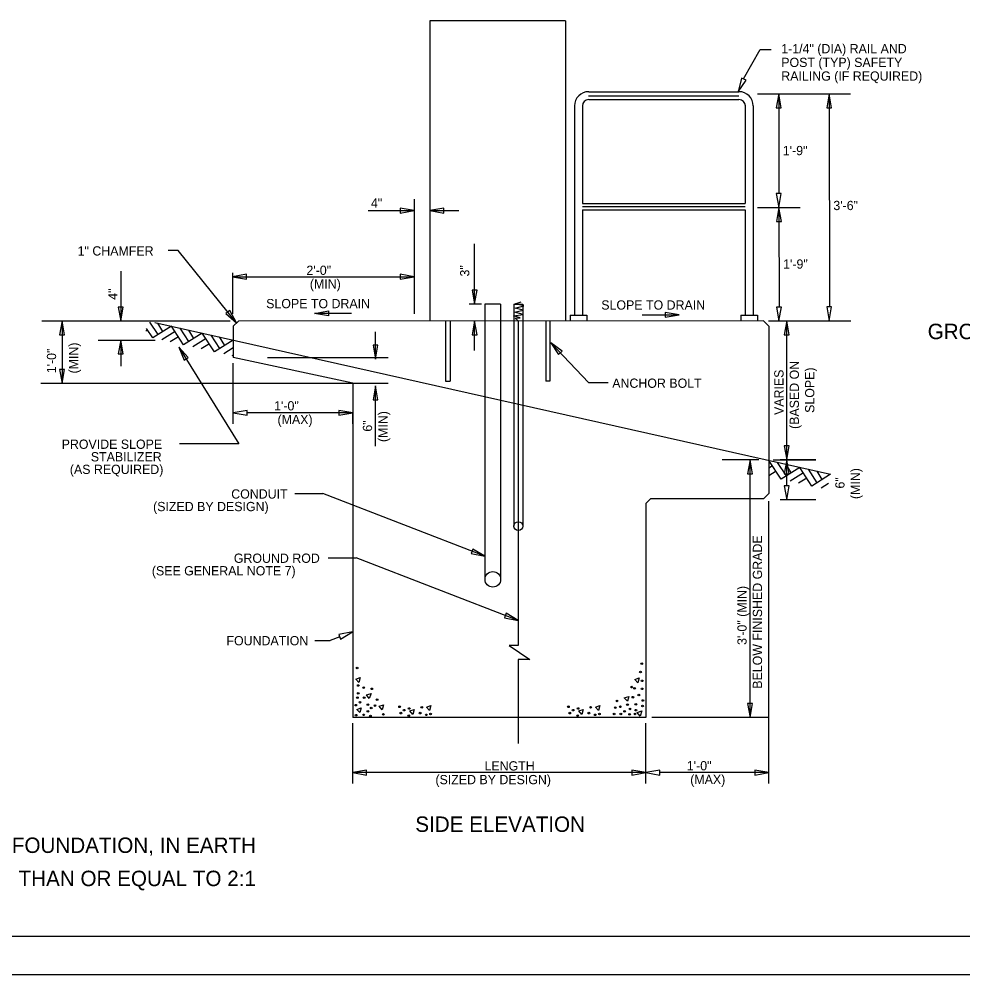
# Model space of a CAD drawing. Extents: x 1299104.8 to 1299141.6, y 239639.8 to 239661.8.
# Drawn here: x 1299117.69 to 1299129.92, y 239639.79 to 239652.18 of the extents above; entities that cross this region are included whole.
import ezdxf

# ---------------------------------------------------------------- set-up
doc = ezdxf.new("R2010")
doc.units = 0
for name, color, linetype in [('GS_plotshape_p', 7, 'Continuous'), ('Level 1', 7, 'Continuous'), ('PTEXT', 7, 'Continuous')]:
    doc.layers.add(name, color=color, linetype=linetype)

msp = doc.modelspace()

# ---------------------------------------------------------------- linework, layer by layer
at = {"layer": 'GS_plotshape_p'}
msp.add_lwpolyline([(1299104.802, 239661.791), (1299138.802, 239661.791), (1299138.802, 239639.791), (1299104.802, 239639.791)], close=True, dxfattribs=at)
at = {"layer": 'Level 1'}
msp.add_lwpolyline([(1299138.302, 239640.291), (1299106.302, 239640.291), (1299106.302, 239661.291), (1299138.302, 239661.291)], close=True, dxfattribs=at)
at = {"layer": 'PTEXT'}
for p, q in [((1299123.016, 239652.158), (1299123.016, 239648.269)), ((1299124.772, 239652.158), (1299123.016, 239652.158)), ((1299124.772, 239652.158), (1299124.772, 239648.269)), ((1299127.055, 239651.418), (1299127.01, 239651.241)), ((1299127.01, 239651.241), (1299127.113, 239651.392)), ((1299127.113, 239651.392), (1299127.055, 239651.418)), ((1299125.073, 239651.189), (1299127.022, 239651.189)), ((1299125.075, 239651.241), (1299127.021, 239651.241)), ((1299125.075, 239651.139), (1299127.021, 239651.139)), ((1299127.262, 239651.212), (1299127.812, 239651.212)), ((1299127.264, 239651.212), (1299128.467, 239651.212)), ((1299127.537, 239651.212), (1299127.505, 239651.032)), ((1299127.537, 239651.212), (1299127.537, 239649.92)), ((1299127.568, 239651.032), (1299127.537, 239651.212)), ((1299128.192, 239651.212), (1299128.16, 239651.032)), ((1299128.192, 239651.212), (1299128.194, 239648.451)), ((1299128.223, 239651.032), (1299128.192, 239651.212)), ((1299124.89, 239651.056), (1299124.89, 239648.345)), ((1299124.992, 239651.056), (1299124.992, 239649.793)), ((1299127.104, 239651.057), (1299127.104, 239649.793)), ((1299127.206, 239651.056), (1299127.206, 239648.345)), ((1299127.505, 239651.032), (1299127.568, 239651.032)), ((1299128.16, 239651.032), (1299128.223, 239651.032)), ((1299127.505, 239649.92), (1299127.537, 239649.74)), ((1299127.568, 239649.92), (1299127.505, 239649.92)), ((1299127.537, 239649.74), (1299127.568, 239649.92)), ((1299122.81, 239649.848), (1299122.81, 239648.363)), ((1299124.992, 239649.793), (1299127.104, 239649.793)), ((1299122.217, 239649.699), (1299122.81, 239649.699)), ((1299122.81, 239649.699), (1299122.63, 239649.731)), ((1299122.63, 239649.731), (1299122.63, 239649.668)), ((1299122.63, 239649.668), (1299122.81, 239649.699)), ((1299123.196, 239649.731), (1299123.016, 239649.699)), ((1299123.016, 239649.699), (1299123.392, 239649.699)), ((1299123.016, 239649.699), (1299123.196, 239649.668)), ((1299123.196, 239649.668), (1299123.196, 239649.731)), ((1299124.992, 239649.753), (1299127.104, 239649.753)), ((1299124.992, 239649.709), (1299124.992, 239648.345)), ((1299124.992, 239649.709), (1299127.104, 239649.709)), ((1299127.104, 239649.709), (1299127.104, 239648.345)), ((1299127.262, 239649.74), (1299127.812, 239649.74)), ((1299127.265, 239649.74), (1299127.815, 239649.74)), ((1299127.54, 239649.74), (1299127.509, 239649.56)), ((1299127.54, 239649.74), (1299127.541, 239648.449)), ((1299127.572, 239649.56), (1299127.54, 239649.74)), ((1299127.509, 239649.56), (1299127.572, 239649.56)), ((1299123.594, 239648.489), (1299123.594, 239649.267)), ((1299119.007, 239648.913), (1299119.007, 239648.269)), ((1299120.458, 239648.891), (1299120.458, 239648.36)), ((1299120.638, 239648.874), (1299120.458, 239648.842)), ((1299120.458, 239648.842), (1299122.81, 239648.842)), ((1299120.458, 239648.842), (1299120.638, 239648.81)), ((1299120.638, 239648.81), (1299120.638, 239648.874)), ((1299122.81, 239648.842), (1299122.63, 239648.874)), ((1299122.63, 239648.874), (1299122.63, 239648.81)), ((1299122.63, 239648.81), (1299122.81, 239648.842)), ((1299123.563, 239648.669), (1299123.594, 239648.489)), ((1299123.626, 239648.669), (1299123.563, 239648.669)), ((1299123.594, 239648.489), (1299123.626, 239648.669)), ((1299118.975, 239648.449), (1299119.007, 239648.269)), ((1299119.038, 239648.449), (1299118.975, 239648.449)), ((1299119.007, 239648.269), (1299119.038, 239648.449)), ((1299123.526, 239648.489), (1299123.683, 239648.489)), ((1299123.932, 239648.488), (1299123.729, 239648.488)), ((1299123.729, 239648.488), (1299123.729, 239648.269)), ((1299123.932, 239648.488), (1299123.932, 239648.269)), ((1299124.103, 239648.488), (1299124.103, 239645.609)), ((1299124.103, 239648.488), (1299124.219, 239648.488)), ((1299124.219, 239648.488), (1299124.219, 239645.609)), ((1299127.509, 239648.449), (1299127.54, 239648.269)), ((1299127.572, 239648.449), (1299127.509, 239648.449)), ((1299127.54, 239648.269), (1299127.572, 239648.449)), ((1299128.16, 239648.451), (1299128.192, 239648.271)), ((1299128.223, 239648.451), (1299128.16, 239648.451)), ((1299128.192, 239648.271), (1299128.223, 239648.451)), ((1299120.422, 239648.405), (1299120.372, 239648.366)), ((1299120.372, 239648.366), (1299120.509, 239648.245)), ((1299120.509, 239648.245), (1299120.422, 239648.405)), ((1299121.52, 239648.366), (1299121.7, 239648.398)), ((1299122, 239648.366), (1299121.52, 239648.366)), ((1299121.7, 239648.334), (1299121.52, 239648.366)), ((1299121.7, 239648.398), (1299121.7, 239648.334)), ((1299124.832, 239648.345), (1299125.05, 239648.345)), ((1299124.832, 239648.345), (1299124.832, 239648.269)), ((1299125.05, 239648.345), (1299125.05, 239648.269)), ((1299125.766, 239648.348), (1299126.245, 239648.348)), ((1299126.245, 239648.348), (1299126.065, 239648.38)), ((1299126.065, 239648.38), (1299126.065, 239648.317)), ((1299126.065, 239648.317), (1299126.245, 239648.348)), ((1299127.046, 239648.345), (1299127.264, 239648.345)), ((1299127.046, 239648.345), (1299127.046, 239648.269)), ((1299127.264, 239648.345), (1299127.264, 239648.269)), ((1299117.983, 239648.269), (1299120.428, 239648.269)), ((1299118.248, 239648.269), (1299118.216, 239648.089)), ((1299118.248, 239648.269), (1299118.248, 239647.461)), ((1299118.279, 239648.089), (1299118.248, 239648.269)), ((1299119.423, 239648.048), (1299119.342, 239648.172)), ((1299119.492, 239648.092), (1299119.386, 239648.253)), ((1299119.665, 239648.201), (1299119.423, 239648.048)), ((1299119.451, 239648.249), (1299128.209, 239646.282)), ((1299119.554, 239648.131), (1299119.49, 239648.24)), ((1299119.823, 239647.958), (1299119.665, 239648.201)), ((1299119.892, 239648.002), (1299119.777, 239648.176)), ((1299120.533, 239648.268), (1299120.465, 239648.201)), ((1299120.465, 239648.201), (1299120.465, 239647.793)), ((1299127.341, 239648.269), (1299120.533, 239648.268)), ((1299123.219, 239648.269), (1299123.219, 239647.49)), ((1299123.277, 239648.269), (1299123.277, 239647.49)), ((1299123.594, 239648.269), (1299123.563, 239648.089)), ((1299123.594, 239647.886), (1299123.594, 239648.269)), ((1299123.626, 239648.089), (1299123.594, 239648.269)), ((1299123.729, 239648.269), (1299123.729, 239644.919)), ((1299123.932, 239648.269), (1299123.932, 239644.919)), ((1299124.161, 239648.269), (1299124.161, 239644.889)), ((1299124.518, 239648.269), (1299124.518, 239647.49)), ((1299124.572, 239648.269), (1299124.572, 239647.488)), ((1299127.341, 239648.269), (1299127.409, 239648.201)), ((1299127.404, 239648.269), (1299127.936, 239648.269)), ((1299127.405, 239648.269), (1299128.47, 239648.271)), ((1299127.409, 239648.201), (1299127.409, 239646.034)), ((1299127.465, 239648.269), (1299127.823, 239648.269)), ((1299127.641, 239648.269), (1299127.609, 239648.089)), ((1299127.641, 239646.469), (1299127.641, 239648.269)), ((1299127.672, 239648.089), (1299127.641, 239648.269)), ((1299118.216, 239648.089), (1299118.279, 239648.089)), ((1299119.357, 239648.152), (1299119.334, 239648.137)), ((1299119.714, 239648.131), (1299119.541, 239648.022)), ((1299119.758, 239648.062), (1299119.649, 239647.998)), ((1299120.065, 239648.111), (1299119.823, 239647.958)), ((1299119.954, 239648.041), (1299119.89, 239648.151)), ((1299120.114, 239648.041), (1299119.942, 239647.932)), ((1299120.224, 239647.868), (1299120.065, 239648.111)), ((1299120.293, 239647.912), (1299120.178, 239648.086)), ((1299120.355, 239647.951), (1299120.29, 239648.061)), ((1299122.31, 239647.774), (1299122.31, 239648.126)), ((1299123.563, 239648.089), (1299123.626, 239648.089)), ((1299127.609, 239648.089), (1299127.672, 239648.089)), ((1299118.716, 239648.021), (1299119.455, 239648.021)), ((1299119.007, 239648.021), (1299118.975, 239647.841)), ((1299119.007, 239648.021), (1299119.007, 239647.681)), ((1299119.038, 239647.841), (1299119.007, 239648.021)), ((1299119.882, 239647.795), (1299119.759, 239647.93)), ((1299119.759, 239647.93), (1299119.828, 239647.761)), ((1299120.158, 239647.972), (1299120.049, 239647.908)), ((1299120.465, 239648.021), (1299120.224, 239647.868)), ((1299120.465, 239647.92), (1299120.342, 239647.842)), ((1299122.278, 239647.954), (1299122.31, 239647.774)), ((1299122.342, 239647.954), (1299122.278, 239647.954)), ((1299122.31, 239647.774), (1299122.342, 239647.954)), ((1299124.729, 239647.878), (1299124.582, 239647.987)), ((1299124.582, 239647.987), (1299124.683, 239647.834)), ((1299118.975, 239647.841), (1299119.038, 239647.841)), ((1299119.828, 239647.761), (1299119.882, 239647.795)), ((1299120.465, 239647.827), (1299120.449, 239647.818)), ((1299122.015, 239647.461), (1299120.465, 239647.793)), ((1299120.909, 239647.793), (1299122.476, 239647.793)), ((1299124.683, 239647.834), (1299124.729, 239647.878)), ((1299120.465, 239646.937), (1299120.465, 239647.721)), ((1299118.216, 239647.641), (1299118.248, 239647.461)), ((1299118.279, 239647.641), (1299118.216, 239647.641)), ((1299118.248, 239647.461), (1299118.279, 239647.641)), ((1299117.973, 239647.461), (1299122.475, 239647.461)), ((1299122.015, 239647.461), (1299122.015, 239643.128)), ((1299122.31, 239647.426), (1299122.278, 239647.246)), ((1299122.31, 239646.647), (1299122.31, 239647.426)), ((1299122.342, 239647.246), (1299122.31, 239647.426)), ((1299123.219, 239647.49), (1299123.277, 239647.49)), ((1299124.572, 239647.49), (1299124.518, 239647.49)), ((1299122.278, 239647.246), (1299122.342, 239647.246)), ((1299120.645, 239647.11), (1299120.465, 239647.079)), ((1299120.465, 239647.079), (1299120.645, 239647.047)), ((1299122.015, 239647.079), (1299120.639, 239647.079)), ((1299120.645, 239647.047), (1299120.645, 239647.11)), ((1299122.015, 239647.078), (1299121.835, 239647.11)), ((1299121.835, 239647.11), (1299121.835, 239647.047)), ((1299121.835, 239647.047), (1299122.015, 239647.078)), ((1299122.015, 239646.937), (1299122.015, 239647.078)), ((1299127.609, 239646.649), (1299127.641, 239646.469)), ((1299127.672, 239646.649), (1299127.609, 239646.649)), ((1299127.641, 239646.469), (1299127.672, 239646.649)), ((1299127.28, 239646.469), (1299126.806, 239646.469)), ((1299127.166, 239646.469), (1299127.134, 239646.289)), ((1299127.166, 239643.128), (1299127.166, 239646.469)), ((1299127.197, 239646.289), (1299127.166, 239646.469)), ((1299127.567, 239646.219), (1299127.409, 239646.461)), ((1299127.465, 239646.469), (1299128.018, 239646.469)), ((1299127.636, 239646.262), (1299127.521, 239646.436)), ((1299128.018, 239646.469), (1299127.554, 239646.469)), ((1299127.641, 239646.469), (1299127.609, 239646.289)), ((1299127.641, 239646.13), (1299127.641, 239646.469)), ((1299127.672, 239646.289), (1299127.641, 239646.469)), ((1299127.458, 239646.391), (1299127.409, 239646.36)), ((1299127.502, 239646.322), (1299127.409, 239646.263)), ((1299127.809, 239646.371), (1299127.567, 239646.219)), ((1299127.698, 239646.302), (1299127.634, 239646.411)), ((1299127.967, 239646.129), (1299127.809, 239646.371)), ((1299128.036, 239646.172), (1299127.922, 239646.346)), ((1299128.099, 239646.212), (1299128.034, 239646.321)), ((1299127.134, 239646.289), (1299127.197, 239646.289)), ((1299127.609, 239646.289), (1299127.672, 239646.289)), ((1299127.858, 239646.301), (1299127.686, 239646.192)), ((1299127.902, 239646.232), (1299127.793, 239646.168)), ((1299128.209, 239646.282), (1299127.967, 239646.129)), ((1299127.609, 239646.132), (1299127.641, 239645.952)), ((1299127.672, 239646.132), (1299127.609, 239646.132)), ((1299127.641, 239645.952), (1299127.672, 239646.132)), ((1299128.182, 239646.163), (1299128.086, 239646.102)), ((1299121.265, 239646.03), (1299121.628, 239646.03)), ((1299123.729, 239645.218), (1299121.628, 239646.03)), ((1299125.815, 239645.904), (1299125.88, 239645.969)), ((1299125.88, 239645.969), (1299127.344, 239645.969)), ((1299127.344, 239645.969), (1299127.409, 239646.034)), ((1299128.018, 239645.952), (1299127.554, 239645.952)), ((1299125.815, 239645.904), (1299125.815, 239643.128)), ((1299127.409, 239642.271), (1299127.409, 239645.931)), ((1299121.698, 239645.197), (1299122.061, 239645.197)), ((1299124.161, 239644.385), (1299122.061, 239645.197)), ((1299123.571, 239645.311), (1299123.549, 239645.252)), ((1299123.549, 239645.252), (1299123.729, 239645.219)), ((1299123.729, 239645.219), (1299123.571, 239645.311)), ((1299124.161, 239644.889), (1299124.161, 239644.062)), ((1299124.004, 239644.479), (1299123.982, 239644.419)), ((1299124.161, 239644.386), (1299124.004, 239644.479)), ((1299123.982, 239644.419), (1299124.161, 239644.386)), ((1299122.014, 239644.239), (1299121.835, 239644.203)), ((1299121.835, 239644.203), (1299121.858, 239644.144)), ((1299121.858, 239644.144), (1299122.014, 239644.239)), ((1299121.524, 239644.126), (1299121.722, 239644.126)), ((1299121.846, 239644.174), (1299121.722, 239644.126)), ((1299124.161, 239643.878), (1299124.161, 239642.791)), ((1299127.134, 239643.309), (1299127.166, 239643.129)), ((1299127.197, 239643.309), (1299127.134, 239643.309)), ((1299127.166, 239643.129), (1299127.197, 239643.309)), ((1299125.815, 239643.128), (1299122.015, 239643.128)), ((1299127.409, 239643.128), (1299125.891, 239643.128)), ((1299122.015, 239642.271), (1299122.015, 239643.055)), ((1299125.815, 239642.271), (1299125.815, 239643.055)), ((1299125.815, 239642.271), (1299125.815, 239643.055)), ((1299122.195, 239642.445), (1299122.015, 239642.413)), ((1299125.815, 239642.413), (1299122.015, 239642.413)), ((1299122.015, 239642.413), (1299122.195, 239642.381)), ((1299122.195, 239642.381), (1299122.195, 239642.445)), ((1299125.815, 239642.413), (1299125.635, 239642.445)), ((1299125.635, 239642.445), (1299125.635, 239642.381)), ((1299125.635, 239642.381), (1299125.815, 239642.413)), ((1299125.995, 239642.445), (1299125.815, 239642.413)), ((1299125.815, 239642.413), (1299125.995, 239642.381)), ((1299127.409, 239642.413), (1299125.989, 239642.413)), ((1299125.995, 239642.381), (1299125.995, 239642.445)), ((1299127.409, 239642.413), (1299127.229, 239642.445)), ((1299127.229, 239642.445), (1299127.229, 239642.381)), ((1299127.229, 239642.381), (1299127.409, 239642.413))]:
    msp.add_line(p, q, dxfattribs=at)
for points in [[(1299127.081, 239651.406), (1299127.295, 239651.789), (1299127.438, 239651.789)], [(1299120.509, 239648.245), (1299119.754, 239649.184), (1299119.623, 239649.181)], [(1299124.161, 239648.269), (1299124.12, 239648.306), (1299124.187, 239648.311), (1299124.101, 239648.335), (1299124.226, 239648.354), (1299124.11, 239648.383), (1299124.226, 239648.407), (1299124.12, 239648.436), (1299124.235, 239648.465), (1299124.12, 239648.493), (1299124.197, 239648.517)], [(1299119.759, 239647.93), (1299120.538, 239646.676), (1299119.77, 239646.676)], [(1299124.582, 239647.987), (1299125.072, 239647.472), (1299125.324, 239647.472)], [(1299124.161, 239644.062), (1299124.041, 239644.062), (1299124.309, 239643.879), (1299124.161, 239643.878)], [(1299122.057, 239643.626), (1299122.113, 239643.645), (1299122.095, 239643.581), (1299122.057, 239643.626)], [(1299125.673, 239643.619), (1299125.73, 239643.641), (1299125.711, 239643.578), (1299125.673, 239643.619)], [(1299122.192, 239643.42), (1299122.252, 239643.439), (1299122.23, 239643.375), (1299122.192, 239643.42)], [(1299125.535, 239643.383), (1299125.595, 239643.401), (1299125.576, 239643.338), (1299125.535, 239643.383)], [(1299122.068, 239643.233), (1299122.125, 239643.255), (1299122.106, 239643.191), (1299122.068, 239643.233)], [(1299122.357, 239643.274), (1299122.413, 239643.293), (1299122.395, 239643.229), (1299122.357, 239643.274)], [(1299122.757, 239643.214), (1299122.813, 239643.233), (1299122.794, 239643.169), (1299122.757, 239643.214)], [(1299122.973, 239643.261), (1299123.029, 239643.283), (1299123.01, 239643.22), (1299122.973, 239643.261)], [(1299124.946, 239643.214), (1299125.002, 239643.233), (1299124.983, 239643.169), (1299124.946, 239643.214)], [(1299125.162, 239643.261), (1299125.219, 239643.283), (1299125.2, 239643.22), (1299125.162, 239643.261)], [(1299125.703, 239643.191), (1299125.763, 239643.214), (1299125.741, 239643.146), (1299125.703, 239643.191)]]:
    msp.add_lwpolyline(points, dxfattribs=at)
for centre, radius in [((1299124.161, 239645.609), 0.0578), ((1299123.831, 239644.919), 0.101)]:
    msp.add_circle(centre, radius, dxfattribs=at)
for centre, radius, start, end in [((1299125.075, 239651.056), 0.185, 90, 180), ((1299125.075, 239651.056), 0.0833, 90, 180), ((1299127.021, 239651.056), 0.185, 0, 90), ((1299127.021, 239651.056), 0.0833, 0, 90)]:
    msp.add_arc(centre, radius, start, end, dxfattribs=at)
for centre in [(1299125.761, 239643.826), (1299122.071, 239643.771), (1299125.745, 239643.717), (1299125.767, 239643.603), (1299122.087, 239643.543), (1299122.157, 239643.516), (1299122.261, 239643.5), (1299125.631, 239643.522), (1299125.669, 239643.505), (1299125.767, 239643.5), (1299122.076, 239643.386), (1299122.087, 239643.44), (1299122.109, 239643.326), (1299122.163, 239643.386), (1299122.331, 239643.359), (1299125.441, 239643.343), (1299125.647, 239643.391), (1299125.723, 239643.419), (1299125.777, 239643.348), (1299122.054, 239643.288), (1299122.212, 239643.294), (1299122.212, 239643.207), (1299122.255, 239643.25), (1299122.304, 239643.283), (1299122.622, 239643.267), (1299122.682, 239643.223), (1299122.747, 239643.245), (1299122.91, 239643.261), (1299124.811, 239643.267), (1299124.871, 239643.223), (1299124.936, 239643.245), (1299125.099, 239643.261), (1299125.419, 239643.256), (1299125.484, 239643.267), (1299125.539, 239643.207), (1299125.577, 239643.294), (1299125.609, 239643.239), (1299125.685, 239643.299), (1299125.685, 239643.223), (1299125.772, 239643.277), (1299122.06, 239643.158), (1299122.157, 239643.163), (1299122.244, 239643.147), (1299122.412, 239643.169), (1299122.638, 239643.185), (1299122.741, 239643.153), (1299122.888, 239643.185), (1299122.969, 239643.163), (1299123.024, 239643.174), (1299124.828, 239643.185), (1299124.931, 239643.153), (1299125.077, 239643.185), (1299125.159, 239643.163), (1299125.213, 239643.174), (1299125.403, 239643.174), (1299125.49, 239643.174), (1299125.604, 239643.169), (1299125.674, 239643.174)]:
    msp.add_ellipse(centre, major_axis=(-0.0115, 0), ratio=0.9, dxfattribs=at)

# ---------------------------------------------------------------- texts
for s, height, p in [('1-1/4" (DIA) RAIL AND ', 0.12, (1299127.57, 239651.739)), ('POST (TYP) SAFETY ', 0.12, (1299127.57, 239651.561)), ('RAILING (IF REQUIRED)', 0.12, (1299127.57, 239651.384)), ('1\'-9"', 0.12, (1299127.59, 239650.418)), ('3\'-6"', 0.12, (1299128.245, 239649.706)), ('1" CHAMFER', 0.12, (1299118.449, 239649.117)), ('2\'-0"', 0.12, (1299121.415, 239648.866)), ('(MIN)', 0.12, (1299121.459, 239648.689)), ('SLOPE TO DRAIN', 0.12, (1299120.893, 239648.434)), ('SLOPE TO DRAIN', 0.12, (1299125.237, 239648.416)), ('GROUND MOUNTED ITS ENCLOSURE ORIENTATION', 0.2, (1299129.468, 239648.033)), ('ANCHOR BOLT', 0.12, (1299125.379, 239647.402)), ('1\'-0"', 0.12, (1299120.996, 239647.109)), ('(MAX)', 0.12, (1299121.04, 239646.931)), ('PROVIDE SLOPE', 0.12, (1299118.242, 239646.611)), ('STABILIZER', 0.12, (1299118.62, 239646.448)), ('(AS REQUIRED)', 0.12, (1299118.348, 239646.285)), ('CONDUIT', 0.12, (1299120.44, 239645.966)), ('(SIZED BY DESIGN)', 0.12, (1299119.427, 239645.803)), ('GROUND ROD', 0.12, (1299120.474, 239645.133)), ('(SEE GENERAL NOTE 7)', 0.12, (1299119.411, 239644.97)), ('FOUNDATION', 0.12, (1299120.378, 239644.064)), ('LENGTH', 0.12, (1299123.723, 239642.441)), ('1\'-0"', 0.12, (1299126.346, 239642.443)), ('(SIZED BY DESIGN)', 0.12, (1299123.087, 239642.263)), ('(MAX)', 0.12, (1299126.39, 239642.265)), ('SIDE ELEVATION', 0.2, (1299122.826, 239641.645)), ('ITS ENCLOSURE FOUNDATION, IN EARTH ', 0.2, (1299115.367, 239641.372)), ('SLOPE GREATER THAN OR EQUAL TO 2:1', 0.2, (1299115.35, 239640.942))]:
    msp.add_text(s, height=height, dxfattribs=at).set_placement(p)
for s, rotation, p in [('4" ', 360, (1299122.251, 239649.738)), ('1\'-9"', 360, (1299127.594, 239648.947)), ('3" ', 90, (1299123.527, 239648.845)), ('4" ', 90, (1299118.965, 239648.543)), ('(MIN)', 90, (1299118.456, 239647.588)), ('1\'-0"', 90, (1299118.17, 239647.591)), ('(BASED ON', 90, (1299127.799, 239646.869)), ('VARIES', 90, (1299127.599, 239647.05)), ('SLOPE)', 90, (1299127.999, 239647.077)), ('(MIN)', 90, (1299122.466, 239646.699)), ('6"', 90, (1299122.266, 239646.834)), ('(MIN)', 90, (1299128.59, 239645.96)), ('6" ', 90, (1299128.39, 239646.096)), ('BELOW FINISHED GRADE', 90, (1299127.321, 239643.501)), ('3\'-0" (MIN)', 90, (1299127.121, 239644.069))]:
    msp.add_text(s, height=0.12, rotation=rotation, dxfattribs=at).set_placement(p)

doc.saveas('drawing.dxf')
